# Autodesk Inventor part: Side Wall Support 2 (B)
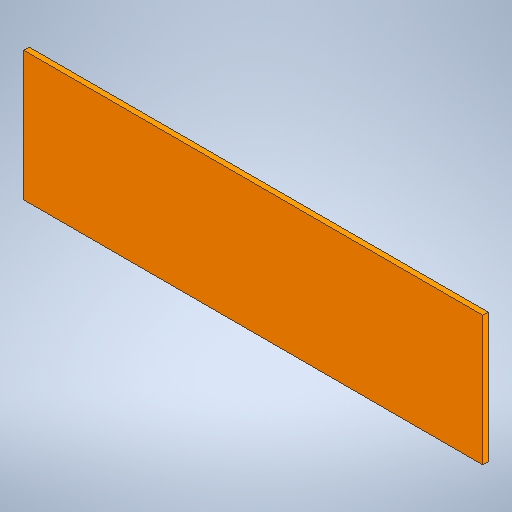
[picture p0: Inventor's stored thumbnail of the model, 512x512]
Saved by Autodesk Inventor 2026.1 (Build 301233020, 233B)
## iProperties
Created: 2026-11
Part Number: Side Wall Support 2 (B)
Material: Generic
Document SubType Name: Modeling
Designer: hp
Density: 1 g/cm^3
Appearance: Default
Author: hp
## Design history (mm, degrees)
sketch "Sketch1"
  geometry: L1 (0, 0)-(425, 0); L2 (425, 0)-(425, 120); L3 (425, 120)-(0, 120); L4 (0, 120)-(0, 0)
  constraints: 8 end point, 2 parallel, 1 horizontal, 1 perpendicular
  dimensions: "d0" = 425 distance of L3.end L2.end; "d1" = 120 distance of L2.end L1.end
extrude "Extrusion1" new body sketch "Sketch1" distance "d2" = 5; taper "d3" = 0 deg
body "Solid1"
